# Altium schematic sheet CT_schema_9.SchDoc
size 287 x 160 mm
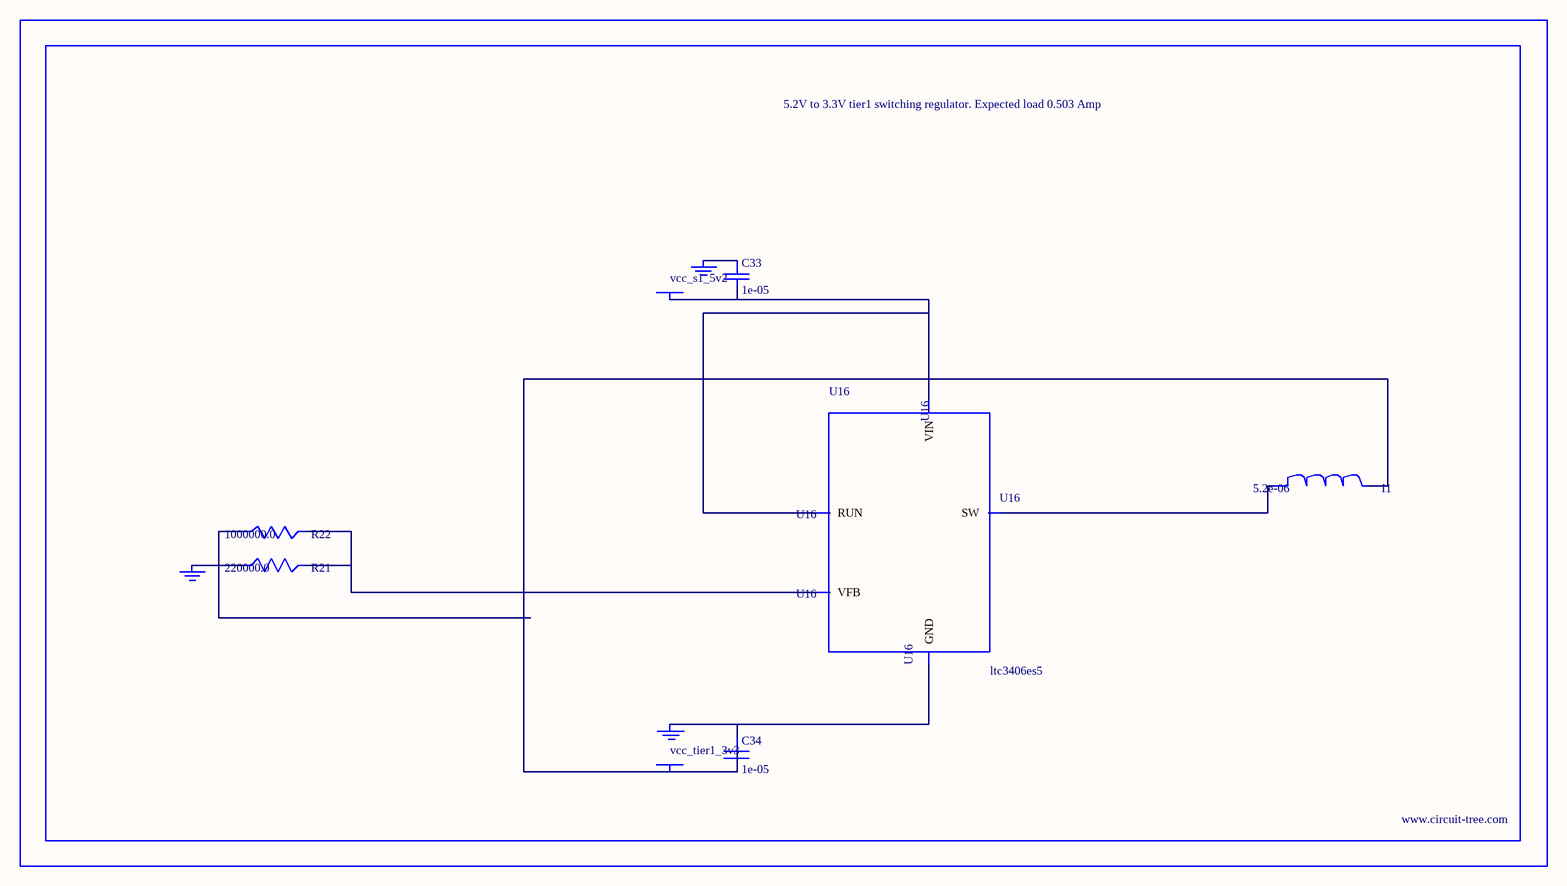
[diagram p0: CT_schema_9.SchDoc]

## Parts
BORDER8  (no value)
C33  1e-05  [C0805]
C34  1e-05  [C0805]
GND_INSTANCE_8_0  (no value)
GND_INSTANCE_8_1  (no value)
GND_INSTANCE_8_2  (no value)
I1  5.2e-06  [DR1040]
POWER_INSTANCE_8_0  vcc_tier1_3v3
POWER_INSTANCE_8_1  vcc_s1_5v2
R21  220000.0  [R0603]
R22  1000000.0  [R0603]
U16  ltc3406es5  [TSOT-23-5]

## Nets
NetC33_1: C33.1 GND_INSTANCE_8_1.0(GND)
NetC33_2: C33.2 POWER_INSTANCE_8_1.0(PWR) U16.1(RUN) U16.4(VIN)
NetC34_1: C34.1 GND_INSTANCE_8_0.0(GND) U16.2(GND)
NetC34_2: C34.2 I1.2 POWER_INSTANCE_8_0.0(PWR) R22.1
NetGND_INSTANCE_8_2_0: GND_INSTANCE_8_2.0(GND) R21.1
NetI1_1: I1.1 U16.3(SW)
NetR21_2: R21.2 R22.2 U16.5(VFB)

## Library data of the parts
BORDER8 = BORDER_PAGE8
C33 C34 = C0805C106K8RACTU
GND_INSTANCE_8_0-GND_INSTANCE_8_2 = GND
I1 = DR1040-5R2-R
POWER_INSTANCE_8_0 POWER_INSTANCE_8_1 = PWR
R21 = RC0603JR-07220KL
R22 = RC0603JR-071ML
